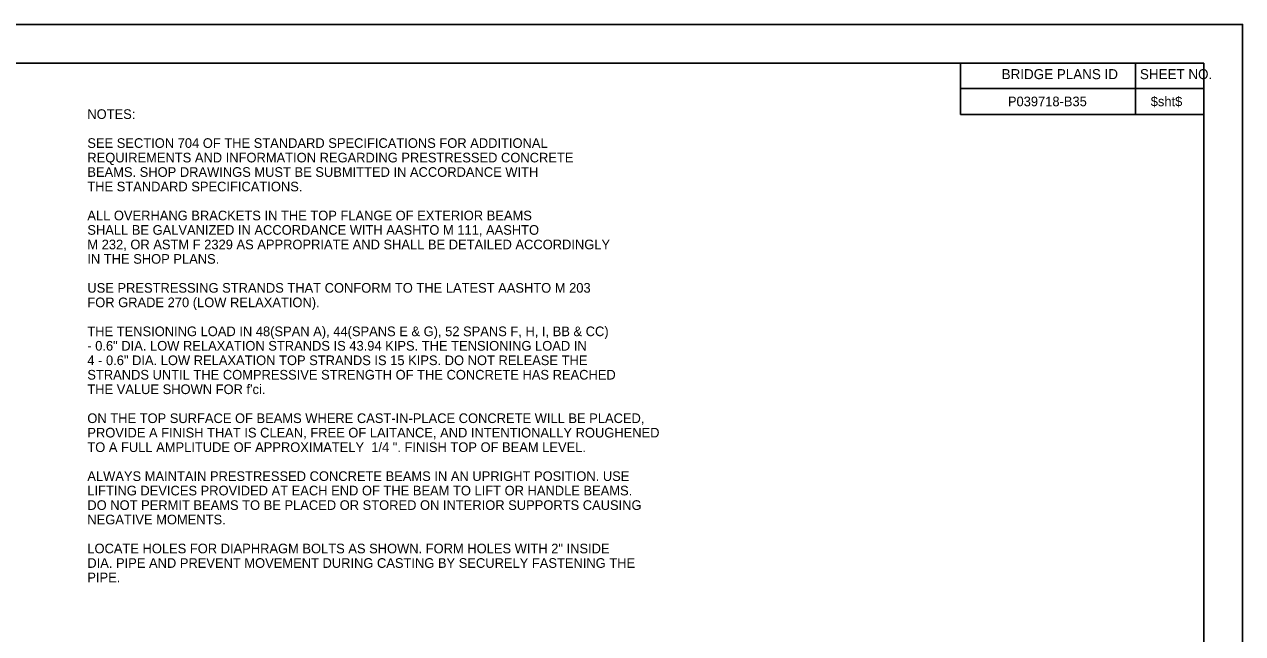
# Model space of a CAD drawing. Extents: x -55.6 to -19.5, y -5.1 to 16.9.
# Drawn here: x -35.36 to -19.58, y 9.02 to 16.91 of the extents above; entities that cross this region are included whole.
import ezdxf

# ---------------------------------------------------------------- set-up
doc = ezdxf.new("R2010")
doc.units = 0
for name, color, linetype in [('BR_BORDER LINES', 7, 'Continuous'), ('BR_TEXT', 7, 'Continuous'), ('Level 31', 7, 'Continuous')]:
    doc.layers.add(name, color=color, linetype=linetype)

msp = doc.modelspace()

# ---------------------------------------------------------------- linework, layer by layer
at = {"layer": 'BR_BORDER LINES'}
for p, q in [((-20.084, 16.408), (-53.75, 16.408)), ((-23.236, 15.742), (-23.236, 16.408)), ((-20.97, 15.742), (-20.97, 16.408)), ((-20.084, -4.592), (-20.084, 16.408)), ((-23.236, 16.079), (-20.084, 16.079)), ((-20.97, 16.079), (-20.084, 16.079)), ((-20.084, 15.742), (-23.236, 15.742))]:
    msp.add_line(p, q, dxfattribs=at)
at = {"layer": 'Level 31'}
msp.add_lwpolyline([(-55.583, -5.092), (-19.583, -5.092), (-19.583, 16.908), (-55.583, 16.908)], close=True, dxfattribs=at)

# ---------------------------------------------------------------- texts
at = {"layer": 'BR_TEXT'}
for s, height, p in [('BRIDGE PLANS ID', 0.13, (-22.705, 16.199)), ('SHEET NO.', 0.13, (-20.914, 16.199)), ('P039718-B35', 0.125, (-22.624, 15.848)), ('$sht$', 0.125, (-20.774, 15.848)), ('NOTES:', 0.125, (-34.549, 15.684)), ('SEE SECTION 704 OF THE STANDARD SPECIFICATIONS FOR ADDITIONAL ', 0.125, (-34.549, 15.309)), ('REQUIREMENTS AND INFORMATION REGARDING PRESTRESSED CONCRETE ', 0.125, (-34.549, 15.121)), ('BEAMS. SHOP DRAWINGS MUST BE SUBMITTED IN ACCORDANCE WITH ', 0.125, (-34.549, 14.934)), ('THE STANDARD SPECIFICATIONS.', 0.125, (-34.549, 14.746)), ('ALL OVERHANG BRACKETS IN THE TOP FLANGE OF EXTERIOR BEAMS', 0.125, (-34.549, 14.371)), ('SHALL BE GALVANIZED IN ACCORDANCE WITH AASHTO M 111, AASHTO', 0.125, (-34.549, 14.184)), ('M 232, OR ASTM F 2329 AS APPROPRIATE AND SHALL BE DETAILED ACCORDINGLY', 0.125, (-34.549, 13.996)), ('IN THE SHOP PLANS.', 0.125, (-34.549, 13.809)), ('USE PRESTRESSING STRANDS THAT CONFORM TO THE LATEST AASHTO M 203', 0.125, (-34.549, 13.434)), ('FOR GRADE 270 (LOW RELAXATION).', 0.125, (-34.549, 13.246)), ('THE TENSIONING LOAD IN 48(SPAN A), 44(SPANS E & G), 52 SPANS F, H, I, BB & CC)', 0.125, (-34.549, 12.871)), ('- 0.6" DIA. LOW RELAXATION STRANDS IS 43.94 KIPS. THE TENSIONING LOAD IN', 0.125, (-34.549, 12.684)), ('4 - 0.6" DIA. LOW RELAXATION TOP STRANDS IS 15 KIPS. DO NOT RELEASE THE', 0.125, (-34.549, 12.496)), ('STRANDS UNTIL THE COMPRESSIVE STRENGTH OF THE CONCRETE HAS REACHED', 0.125, (-34.549, 12.309)), ("THE VALUE SHOWN FOR f'ci.", 0.125, (-34.549, 12.121)), ('ON THE TOP SURFACE OF BEAMS WHERE CAST-IN-PLACE CONCRETE WILL BE PLACED, ', 0.125, (-34.549, 11.746)), ('PROVIDE A FINISH THAT IS CLEAN, FREE OF LAITANCE, AND INTENTIONALLY ROUGHENED ', 0.125, (-34.549, 11.559)), ('TO A FULL AMPLITUDE OF APPROXIMATELY  1/4 ". FINISH TOP OF BEAM LEVEL.', 0.125, (-34.549, 11.371)), ('ALWAYS MAINTAIN PRESTRESSED CONCRETE BEAMS IN AN UPRIGHT POSITION. USE ', 0.125, (-34.549, 10.996)), ('LIFTING DEVICES PROVIDED AT EACH END OF THE BEAM TO LIFT OR HANDLE BEAMS.', 0.125, (-34.549, 10.809)), ('DO NOT PERMIT BEAMS TO BE PLACED OR STORED ON INTERIOR SUPPORTS CAUSING ', 0.125, (-34.549, 10.621)), ('NEGATIVE MOMENTS.', 0.125, (-34.549, 10.434)), ('LOCATE HOLES FOR DIAPHRAGM BOLTS AS SHOWN. FORM HOLES WITH 2" INSIDE', 0.125, (-34.549, 10.059)), ('DIA. PIPE AND PREVENT MOVEMENT DURING CASTING BY SECURELY FASTENING THE', 0.125, (-34.549, 9.871)), ('PIPE.', 0.125, (-34.549, 9.684))]:
    msp.add_text(s, height=height, dxfattribs=at).set_placement(p)

doc.saveas('drawing.dxf')
